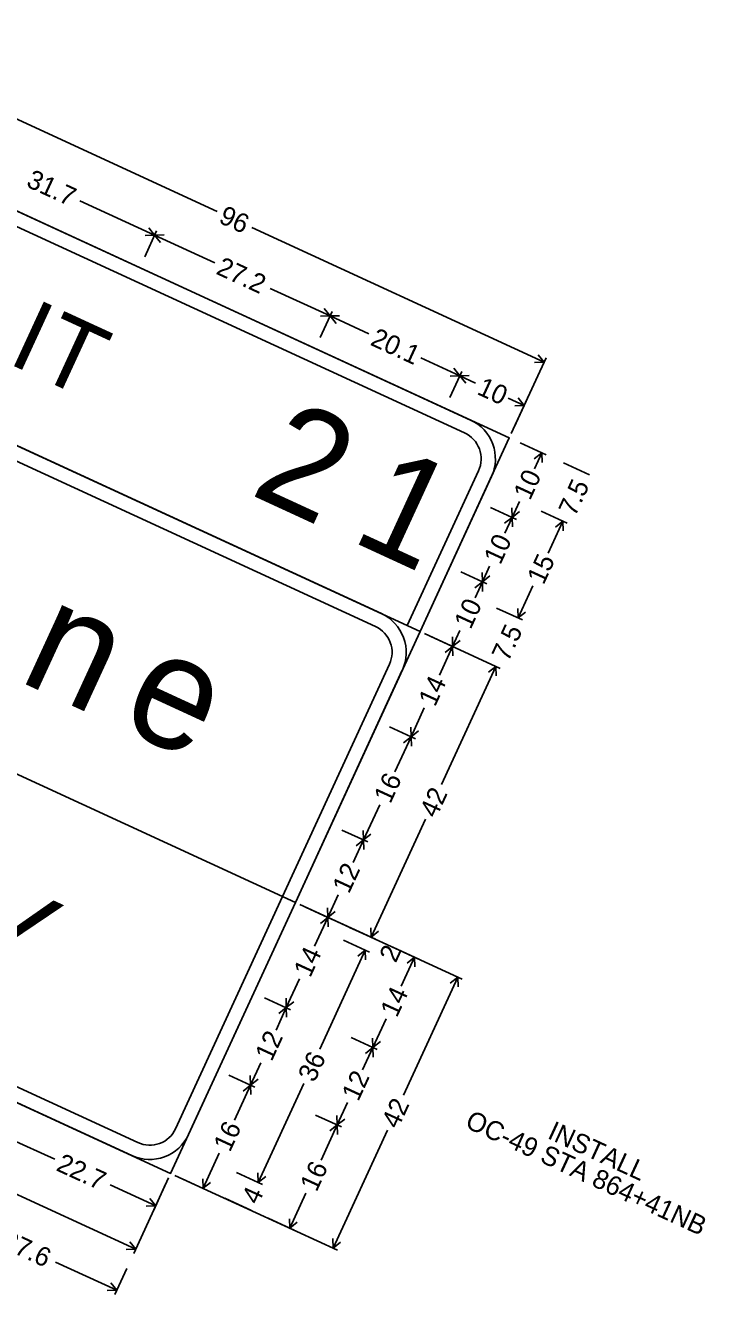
# Model space of a CAD drawing. Extents: x 653488 to 653868, y 428816 to 429028.
# Drawn here: x 653525.19 to 653535.89, y 428985.17 to 429005.09 of the extents above; entities that cross this region are included whole.
import ezdxf

# ---------------------------------------------------------------- set-up
doc = ezdxf.new("R2010")
doc.units = 0
doc.layers.add('S_SIGN', color=7, linetype='Continuous')

msp = doc.modelspace()

# ---------------------------------------------------------------- linework, layer by layer
at = {"layer": 'S_SIGN'}
for p, q in [((653528.207, 429002.166), (653523.619, 429004.279)), ((653526.052, 429002.335), (653527.224, 429001.795)), ((653527.255, 429001.863), (653527.068, 429001.455)), ((653527.075, 429001.79), (653527.224, 429001.795)), ((653527.131, 429001.912), (653527.224, 429001.795)), ((653527.374, 429001.8), (653527.224, 429001.795)), ((653528.167, 429001.361), (653527.224, 429001.795)), ((653527.318, 429001.678), (653527.224, 429001.795)), ((653528.75, 429001.916), (653533.339, 428999.803)), ((653529.036, 429000.961), (653529.978, 429000.527)), ((653529.434, 428991.324), (653508.779, 429000.835)), ((653529.434, 428991.324), (653508.779, 429000.835)), ((653530.009, 429000.595), (653529.822, 429000.187)), ((653529.884, 429000.643), (653529.978, 429000.527)), ((653529.828, 429000.522), (653529.978, 429000.527)), ((653530.128, 429000.531), (653529.978, 429000.527)), ((653530.587, 429000.246), (653529.978, 429000.527)), ((653530.072, 429000.41), (653529.978, 429000.527)), ((653531.404, 428999.87), (653532.013, 428999.589)), ((653533.37, 428999.871), (653532.822, 428998.681)), ((653533.189, 428999.798), (653533.339, 428999.803)), ((653533.245, 428999.919), (653533.339, 428999.803)), ((653532.044, 428999.657), (653531.857, 428999.25)), ((653532.044, 428999.657), (653531.857, 428999.25)), ((653531.864, 428999.585), (653532.013, 428999.589)), ((653531.919, 428999.706), (653532.013, 428999.589)), ((653532.163, 428999.594), (653532.013, 428999.589)), ((653532.263, 428999.474), (653532.013, 428999.589)), ((653532.107, 428999.473), (653532.013, 428999.589)), ((653532.776, 428999.238), (653533.026, 428999.123)), ((653533.057, 428999.191), (653532.869, 428998.783)), ((653532.932, 428999.24), (653533.026, 428999.123)), ((653532.876, 428999.118), (653533.026, 428999.123)), ((653533.369, 428998.347), (653532.961, 428998.535)), ((653533.184, 428998.285), (653533.3, 428998.379)), ((653533.186, 428998.129), (653533.3, 428998.379)), ((653533.305, 428998.229), (653533.3, 428998.379)), ((653534.048, 428998.034), (653533.64, 428998.222)), ((653532.949, 428997.616), (653532.834, 428997.366)), ((653532.902, 428997.335), (653532.494, 428997.523)), ((653532.829, 428997.516), (653532.834, 428997.366)), ((653532.951, 428997.46), (653532.834, 428997.366)), ((653533.698, 428997.275), (653533.291, 428997.463)), ((653532.717, 428997.273), (653532.834, 428997.366)), ((653532.719, 428997.117), (653532.834, 428997.366)), ((653532.839, 428997.217), (653532.834, 428997.366)), ((653533.399, 428996.804), (653533.63, 428997.306)), ((653533.514, 428997.213), (653533.63, 428997.306)), ((653533.635, 428997.157), (653533.63, 428997.306)), ((653532.483, 428996.603), (653532.368, 428996.354)), ((653532.436, 428996.322), (653532.028, 428996.51)), ((653532.436, 428996.322), (653532.028, 428996.51)), ((653532.363, 428996.503), (653532.368, 428996.354)), ((653532.485, 428996.447), (653532.368, 428996.354)), ((653532.251, 428996.26), (653532.368, 428996.354)), ((653532.253, 428996.104), (653532.368, 428996.354)), ((653532.373, 428996.204), (653532.368, 428996.354)), ((653533.162, 428996.29), (653532.931, 428995.788)), ((653532.999, 428995.756), (653532.591, 428995.944)), ((653532.999, 428995.756), (653532.591, 428995.944)), ((653532.926, 428995.937), (653532.931, 428995.788)), ((653533.048, 428995.881), (653532.931, 428995.788)), ((653532.017, 428995.591), (653531.902, 428995.341)), ((653532.649, 428994.997), (653531.46, 428995.545)), ((653531.97, 428995.31), (653531.562, 428995.498)), ((653531.97, 428995.31), (653531.562, 428995.498)), ((653531.897, 428995.491), (653531.902, 428995.341)), ((653532.019, 428995.435), (653531.902, 428995.341)), ((653531.693, 428994.888), (653531.902, 428995.341)), ((653531.785, 428995.248), (653531.902, 428995.341)), ((653531.907, 428995.192), (653531.902, 428995.341)), ((653532.649, 428994.997), (653532.242, 428995.185)), ((653531.729, 428993.176), (653532.581, 428995.028)), ((653532.465, 428994.935), (653532.581, 428995.028)), ((653532.586, 428994.879), (653532.581, 428995.028)), ((653531.457, 428994.377), (653531.249, 428993.924)), ((653531.317, 428993.893), (653530.909, 428994.08)), ((653531.244, 428994.073), (653531.249, 428993.924)), ((653531.366, 428994.017), (653531.249, 428993.924)), ((653530.995, 428993.373), (653531.249, 428993.924)), ((653531.132, 428993.83), (653531.249, 428993.924)), ((653531.254, 428993.774), (653531.249, 428993.924)), ((653530.757, 428992.855), (653530.503, 428992.304)), ((653531.476, 428992.628), (653530.623, 428990.776)), ((653530.571, 428992.273), (653530.163, 428992.46)), ((653530.571, 428992.273), (653530.163, 428992.46)), ((653530.498, 428992.453), (653530.503, 428992.304)), ((653530.62, 428992.397), (653530.503, 428992.304)), ((653530.341, 428991.952), (653530.503, 428992.304)), ((653530.386, 428992.21), (653530.503, 428992.304)), ((653530.508, 428992.154), (653530.503, 428992.304)), ((653530.105, 428991.441), (653529.943, 428991.089)), ((653530.691, 428990.745), (653529.502, 428991.292)), ((653532.05, 428990.119), (653529.502, 428991.292)), ((653530.011, 428991.058), (653529.604, 428991.245)), ((653530.011, 428991.058), (653529.604, 428991.245)), ((653529.939, 428991.239), (653529.943, 428991.089)), ((653529.735, 428990.636), (653529.943, 428991.089)), ((653529.827, 428990.995), (653529.943, 428991.089)), ((653530.06, 428991.183), (653529.943, 428991.089)), ((653529.948, 428990.939), (653529.943, 428991.089)), ((653530.691, 428990.745), (653530.283, 428990.932)), ((653530.618, 428990.926), (653530.623, 428990.776)), ((653530.74, 428990.87), (653530.623, 428990.776)), ((653530.598, 428990.542), (653530.19, 428990.73)), ((653531.371, 428990.432), (653530.963, 428990.619)), ((653516.98, 428990.463), (653526.928, 428985.882)), ((653529.815, 428989.022), (653530.53, 428990.573)), ((653530.413, 428990.48), (653530.53, 428990.573)), ((653530.535, 428990.424), (653530.53, 428990.573)), ((653531.094, 428990.01), (653531.303, 428990.463)), ((653531.186, 428990.369), (653531.303, 428990.463)), ((653531.307, 428990.313), (653531.303, 428990.463)), ((653529.499, 428990.124), (653529.291, 428989.672)), ((653531.129, 428988.298), (653531.982, 428990.15)), ((653531.865, 428990.056), (653531.982, 428990.15)), ((653531.987, 428990), (653531.982, 428990.15)), ((653529.359, 428989.64), (653528.951, 428989.828)), ((653529.286, 428989.821), (653529.291, 428989.672)), ((653529.129, 428989.32), (653529.291, 428989.672)), ((653529.174, 428989.578), (653529.291, 428989.672)), ((653529.407, 428989.765), (653529.291, 428989.672)), ((653529.295, 428989.522), (653529.291, 428989.672)), ((653530.858, 428989.498), (653530.65, 428989.046)), ((653530.718, 428989.014), (653530.31, 428989.202)), ((653530.488, 428988.694), (653530.65, 428989.046)), ((653530.533, 428988.952), (653530.65, 428989.046)), ((653530.645, 428989.195), (653530.65, 428989.046)), ((653530.767, 428989.139), (653530.65, 428989.046)), ((653530.655, 428988.896), (653530.65, 428989.046)), ((653528.799, 428988.425), (653528.391, 428988.613)), ((653528.799, 428988.425), (653528.391, 428988.613)), ((653528.893, 428988.808), (653528.731, 428988.457)), ((653528.477, 428987.905), (653528.731, 428988.457)), ((653528.614, 428988.363), (653528.731, 428988.457)), ((653528.726, 428988.606), (653528.731, 428988.457)), ((653528.848, 428988.55), (653528.731, 428988.457)), ((653528.736, 428988.307), (653528.731, 428988.457)), ((653529.566, 428988.48), (653528.851, 428986.929)), ((653530.252, 428988.182), (653530.09, 428987.831)), ((653530.158, 428987.799), (653529.751, 428987.987)), ((653530.158, 428987.799), (653529.751, 428987.987)), ((653529.836, 428987.279), (653530.09, 428987.831)), ((653529.974, 428987.737), (653530.09, 428987.831)), ((653530.086, 428987.98), (653530.09, 428987.831)), ((653530.207, 428987.924), (653530.09, 428987.831)), ((653530.095, 428987.681), (653530.09, 428987.831)), ((653525.655, 428987.292), (653524.94, 428987.621)), ((653530.877, 428987.749), (653530.024, 428985.898)), ((653528.239, 428987.388), (653527.985, 428986.837)), ((653530.092, 428985.866), (653527.543, 428987.04)), ((653528.919, 428986.897), (653528.511, 428987.085)), ((653528.919, 428986.897), (653528.511, 428987.085)), ((653528.846, 428987.078), (653528.851, 428986.929)), ((653528.968, 428987.022), (653528.851, 428986.929)), ((653526.526, 428986.891), (653527.241, 428986.562)), ((653526.896, 428985.814), (653527.444, 428987.003)), ((653527.209, 428986.494), (653527.397, 428986.901)), ((653528.053, 428986.805), (653527.645, 428986.993)), ((653527.98, 428986.986), (653527.985, 428986.837)), ((653528.102, 428986.93), (653527.985, 428986.837)), ((653527.147, 428986.678), (653527.241, 428986.562)), ((653528.733, 428986.492), (653528.325, 428986.68)), ((653529.598, 428986.762), (653529.344, 428986.211)), ((653527.091, 428986.557), (653527.241, 428986.562)), ((653529.412, 428986.179), (653529.005, 428986.367)), ((653529.34, 428986.36), (653529.344, 428986.211)), ((653529.461, 428986.304), (653529.344, 428986.211)), ((653530.019, 428986.047), (653530.024, 428985.898)), ((653526.778, 428985.877), (653526.928, 428985.882)), ((653526.834, 428985.999), (653526.928, 428985.882)), ((653530.141, 428985.991), (653530.024, 428985.898)), ((653525.668, 428985.68), (653526.63, 428985.236)), ((653526.599, 428985.168), (653526.787, 428985.576)), ((653526.481, 428985.232), (653526.63, 428985.236)), ((653526.537, 428985.353), (653526.63, 428985.236))]:
    msp.add_line(p, q, dxfattribs=at)
for points in [[(653529.434, 428991.324), (653531.392, 428995.576), (653510.738, 429005.088), (653508.779, 429000.835), (653508.779, 429000.835), (653508.779, 429000.835)], [(653511.345, 429004.808), (653530.785, 428995.856)], [(653530.691, 428995.653), (653511.252, 429004.606)], [(653531.392, 428995.576), (653532.791, 428998.613), (653523.071, 429003.09), (653521.672, 429000.052), (653521.672, 429000.052), (653521.672, 429000.052)], [(653523.679, 429002.81), (653532.183, 428998.893)], [(653532.09, 428998.691), (653523.585, 429002.607)], [(653532.09, 428998.691), (653532.09, 428998.691), (653532.09, 428998.691)], [(653531.19, 428995.669), (653532.309, 428998.099)], [(653532.511, 428998.006), (653531.392, 428995.576)], [(653506.821, 428996.583), (653527.475, 428987.071), (653529.434, 428991.324)], [(653507.522, 428996.506), (653526.961, 428987.554)], [(653526.868, 428987.351), (653507.429, 428996.303)], [(653530.691, 428995.653), (653530.691, 428995.653), (653530.691, 428995.653)], [(653531.19, 428995.669), (653531.19, 428995.669), (653531.19, 428995.669)], [(653529.231, 428991.417), (653530.91, 428995.062)], [(653531.112, 428994.969), (653529.434, 428991.324)], [(653527.553, 428987.772), (653529.231, 428991.417)], [(653529.231, 428991.417), (653529.231, 428991.417), (653529.231, 428991.417)], [(653529.434, 428991.324), (653527.755, 428987.679)], [(653527.553, 428987.772), (653527.553, 428987.772), (653527.553, 428987.772)]]:
    msp.add_lwpolyline(points, dxfattribs=at)
for centre, radius, start, end in [((653531.904, 428998.286), 0.669, 335.2727, 65.2729), ((653531.904, 428998.286), 0.446, 335.2727, 65.2729), ((653530.505, 428995.248), 0.669, 335.2727, 65.2729), ((653530.505, 428995.248), 0.446, 335.2727, 65.2729), ((653527.148, 428987.959), 0.669, 245.2728, 335.273), ((653527.148, 428987.959), 0.446, 245.2728, 335.273)]:
    msp.add_arc(centre, radius, start, end, dxfattribs=at)

# ---------------------------------------------------------------- texts
for s, height, rotation, p in [('31.7', 0.2993, 335.2727, (653525.192, 429002.566)), ('96', 0.2993, 335.2727, (653528.213, 429001.999)), ('27.2', 0.2993, 335.2727, (653528.172, 429001.194)), ('I', 1.115, 335.2727, (653524.892, 428999.797)), ('T', 1.115, 335.2727, (653525.308, 428999.605)), ('20.1', 0.2993, 335.2727, (653530.593, 429000.079)), ('10', 0.2993, 335.2727, (653532.268, 428999.307)), ('2', 1.672, 335.2727, (653528.694, 428997.739)), ('1', 1.672, 335.2727, (653530.274, 428997.011)), ('10', 0.2993, 65.2729, (653533.116, 428997.621)), ('7.5', 0.2993, 65.2729, (653533.823, 428997.367)), ('10', 0.2993, 65.2729, (653532.65, 428996.609)), ('15', 0.2993, 65.2729, (653533.329, 428996.295)), ('n', 1.783, 335.2727, (653525.052, 428994.814)), ('10', 0.2993, 65.2729, (653532.184, 428995.596)), ('7.5', 0.2993, 65.2729, (653532.774, 428995.089)), ('e', 1.783, 335.2727, (653526.624, 428994.09)), ('14', 0.2993, 65.2729, (653531.625, 428994.382)), ('16', 0.2993, 65.2729, (653530.924, 428992.861)), ('42', 0.2993, 65.2729, (653531.643, 428992.633)), ('12', 0.2993, 65.2729, (653530.273, 428991.446)), ('Y', 1.338, 335.2727, (653524.195, 428990.546)), ('14', 0.2993, 65.2729, (653529.666, 428990.13)), ('2', 0.299, 65.2729, (653531.009, 428990.362)), ('14', 0.2993, 65.2729, (653531.026, 428989.504)), ('12', 0.2993, 65.2729, (653529.06, 428988.814)), ('36', 0.2993, 65.2729, (653529.733, 428988.486)), ('12', 0.2993, 65.2729, (653530.42, 428988.188)), ('42', 0.2993, 65.2729, (653531.044, 428987.755)), ('OC-49 STA 864+41NB', 0.3, 335.2593, (653532.081, 428987.8)), ('16', 0.2993, 65.2729, (653528.406, 428987.393)), ('INSTALL', 0.3, 335.2593, (653533.374, 428987.628)), ('22.7', 0.2993, 335.2727, (653525.661, 428987.124)), ('16', 0.2993, 65.2729, (653529.765, 428986.767)), ('4', 0.299, 65.2729, (653528.849, 428986.566)), ('27.6', 0.2993, 335.2727, (653524.799, 428985.915))]:
    msp.add_text(s, height=height, rotation=rotation, dxfattribs=at).set_placement(p)

doc.saveas('drawing.dxf')
